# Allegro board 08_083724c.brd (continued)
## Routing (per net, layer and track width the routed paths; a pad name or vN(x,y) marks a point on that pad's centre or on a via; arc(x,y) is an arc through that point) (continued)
PB_07/TM0_TMR0/SPI2_SEL4B/FPLL2: length 59.8
  TOP w0.14: v1(17.86,59.11) 17.49,59.11 17.22,59.37 17.22,60.67 17.08,60.81 R41.2 ; U1.N6 v1(46.15,51.82)
  L10_SIG4 w0.114: v1(46.15,51.82) 46.56,52.22 47.14,52.22 47.35,52.43 47.35,54.36 47.6,54.61 47.95,54.61 48.13,54.8 48.13,55.19 47.9,55.42 47.57,55.42 47.37,55.63 47.37,56.01 47.02,56.36 47.02,56.77 46.51,57.28 46.51,57.56 46.28,57.78 46,57.78 45.72,58.06 45.72,58.37 45.52,58.57 44.81,58.57 43.87,59.51 43.15,59.51 42.02,60.64 34.87,60.64 34.76,60.64 34.58,60.64 33.78,59.84 33.78,58.88 33.53,58.62 32.18,58.62 32.03,58.47 30.43,58.47 30.43,58.47 29.21,58.47 28.5,57.76 28.5,56.54 28.5,56.54 28.5,55.95 28.5,55.94 27.84,55.28 27.84,54.71 26.23,53.11 23.83,53.11 17.86,59.08 v1(17.86,59.11)
  BOTTOM w0.14: v1(17.86,59.11) 18.16,59.11 18.62,59.57 18.62,61.77 16.5,63.9 P8.23
PB_08/TMR1/SPI1_SEL4B/FPLL3_REF: length 57.9
  TOP w0.14: U1.L3 v1(48.55,49.42)
  L10_SIG4 w0.114: v1(17.22,64.31) 20.9,60.63 20.9,60.02 23.22,57.71 23.47,57.71 25.35,59.59 25.35,59.86 25.35,59.86 25.35,60.76 27.46,62.87 38.56,62.87 38.98,63.28 43.01,63.28 43.76,62.53 46.56,62.53 48.11,60.99 49.02,60.99 50.62,59.39 50.62,58.73 51.82,57.53 51.82,52.3 50.52,51 50.14,51 v1(48.55,49.42)
  BOTTOM w0.14: v1(17.22,64.31) 16.87,64.66 16.87,68.2 P8.25
PB_09/TM0_TMR2/EMSIO_WP/ETH0_PT: length 25.7
  TOP w0.14: U1.M3 v1(48.55,51.02)
  L3_SIG1 w0.114: v1(40.5,66.55) 40.2,66.55 40.08,66.44 40.08,63.27 40.41,62.94 40.41,61.01 41.5,59.92 41.5,55.42 41.76,55.16 41.76,54 41.94,53.82 44.04,53.82 44.15,53.71 44.15,51.69 44.42,51.41 46.46,51.41 46.56,51.31 46.56,50.88 46.81,50.62 47.88,50.62 48.2,50.94 v1(48.55,51.02)
  BOTTOM w0.14: P8.119 v1(40.5,66.55)
PB_10/TM0_TMR3/SPI1_D2: length 48.1
  TOP w0.14: U1.K3 v1(48.55,48.62)
  L10_SIG4 w0.114: v1(48.55,48.62) 48.43,48.98 48.16,49.25 48.16,49.68 48.97,50.49 48.97,51.18 49.2,51.41 50.37,51.41 50.6,51.64 50.6,56.1 50.48,56.21 48.39,56.21 48.16,56.44 48.16,57.61 47.95,57.81 47.57,57.81 47.35,58.04 47.35,58.32 47.04,58.62 46.79,58.62 46.53,58.88 46.53,59.96 45.54,60.95 42.94,60.95 42.78,61.1 42.61,61.28 30.19,61.28 27.86,58.95 27.86,56.41 26.82,55.37 26.2,55.37 v2(24.79,53.96)
  BOTTOM w0.14: U6.C4 22.16,54.91 24.66,54.91 R47.2 v2(24.79,53.96)
PB_11/TM0_TMR4/SPI1_D3: length 51.7
  TOP w0.14: U1.L2 v1(49.35,49.42)
  L10_SIG4 w0.114: v1(49.35,49.42) 49.7,49.42 52.13,51.85 52.13,58.93 48.21,62.85 43.89,62.85 43.14,63.6 38.81,63.6 38.39,63.18 27.17,63.18 23.32,59.33 v2(23.32,58.34)
  BOTTOM w0.14: U6.D4 22.17,55.93 R48.2 24.79,56.75 24.59,56.95 23.95,56.95 23.32,57.58 v2(23.32,58.34)
PB_12/TM0_TMR5/SPI5_CLK/PWM0__1: length 57.6
  TOP w0.14: U1.M6 v1(46.15,51.02)
  L10_SIG4 w0.114: v1(46.15,51.02) 46.54,51.41 48.69,51.41 48.97,51.69 48.97,55.17 48.72,55.42 48.35,55.42 48.16,55.62 48.16,55.96 47.88,56.24 47.65,56.24 47.37,56.51 47.37,57.53 47.09,57.81 46.74,57.81 46.53,58.01 46.53,58.41 46.34,58.6 45.95,58.6 45.57,58.98 45.16,58.98 44.91,59.23 44.91,59.8 44.08,60.63 42.81,60.63 42.48,60.96 33.58,60.96 32.31,59.69 29.11,59.69 28.18,58.76 28.18,58.32 28.18,58.31 28.18,56.07 27.52,55.41 27.52,55.15 27.52,54.84 26.1,53.42 23.96,53.42 18.36,59.02 18.36,59.99 18.24,60.12 v1(17.86,60.12)
  BOTTOM w0.14: R178.2 14.94,60.12 v1(17.86,60.12)
PB_12/TM0_TMR5/SPI5_CLK/PWM0_DH: length 5
  BOTTOM w0.14: R178.1 12.52,64.81 12.52,65.61 12.97,66.07 13.23,66.07 13.5,66.33 P8.11
PB_13/TM0_TMR6/SPI5_CITO/PWM0_D: length 57
  TOP w0.14: U1.K2 v1(49.35,48.62)
  L10_SIG4 w0.114: v1(14,66.55) 13.73,66.55 13.61,66.43 13.61,65.41 14.33,64.69 17.4,64.69 17.65,64.44 20.19,64.44 20.7,63.93 43.26,63.93 44.02,63.17 48.4,63.17 52.45,59.12 52.45,51.72 v1(49.35,48.62)
  BOTTOM w0.14: P8.13 v1(14,66.55)
PB_14/TM0_TMR7/SPI5_COTI/PWM0_S: length 59.7
  TOP w0.14: U1.L4 v1(47.75,49.42)
  L10_SIG4 w0.114: v1(47.75,49.42) 47.85,49.05 48.16,48.74 48.16,48.49 48.41,48.23 49.53,48.23 52.79,51.49 52.79,59.26 48.55,63.5 44.19,63.5 43.5,64.19 20.88,64.19 20.37,64.69 17.79,64.69 17.52,64.96 17.51,64.96 16.99,65.48 14.61,65.48 v1(14,66.09)
  BOTTOM w0.14: P8.15 14.5,66.33 14.25,66.09 v1(14,66.09)
PB_15/TM0_TMR8/SPI5_SEL1B/PWM0_: length 62.5
  TOP w0.14: U1.L5 v1(46.95,49.42)
  L10_SIG4 w0.114: v1(46.95,49.42) 47.37,49 47.37,48.46 47.62,48.21 47.93,48.21 48.16,47.98 48.16,47.65 48.39,47.42 49.5,47.42 49.73,47.65 49.73,47.93 53.11,51.3 53.11,59.39 48.67,63.83 44.31,63.83 43.71,64.43 21.86,64.43 21.51,64.77 21.51,66.5 21.07,66.94 16.86,66.94 16.01,66.09 15.45,66.09 v1(15,66.55)
  BOTTOM w0.14: P8.17 v1(15,66.55)
PC_00/SPI2_CITO_D1: length 35.4
  TOP w0.14: P8.94 34.25,66.84 34.13,66.73 34.13,65.48 34.01,65.35 33.8,65.35 v1(33.5,65.05) ; U1.U5 v1(46.95,55.02)
  L5_SIG2 w0.114: v1(46.95,55.02) 47.36,55.42 47.93,55.42 48.16,55.65 48.16,55.96 48.41,56.21 48.67,56.21 48.95,56.49 48.95,56.77 49.2,57.02 49.48,57.02 49.73,57.28 49.73,58.01 50.52,58.8 50.52,59.97 48.79,61.7 47.21,61.7 44.29,64.62 42.19,64.62 41.25,65.56 41.25,66.85 40.69,67.41 33.7,67.41 32.67,66.38 32.67,65.46 33.09,65.05 v1(33.5,65.05)
PC_01/SPI2_COTI_D0: length 29.1
  TOP w0.14: P8.96 34.75,66.79 34.85,66.69 34.85,65.72 34.71,65.58 v1(34.5,65.58) ; U1.V4 v1(47.75,55.82)
  L5_SIG2 w0.114: v1(47.75,55.82) 47.75,56.13 48.16,56.54 48.16,56.85 48.97,57.66 48.97,58.32 49.25,58.6 49.62,58.6 49.73,58.71 49.73,60.23 48.6,61.37 47.09,61.37 44.17,64.29 41.91,64.29 40.92,65.28 40.92,66.78 40.59,67.11 35.19,67.11 34.87,66.79 34.87,65.96 v1(34.5,65.58)
PC_02/SPI2_D2: length 33.8
  TOP w0.14: P8.98 35.25,66.84 35.13,66.73 35.13,65.46 34.75,65.07 v1(34.5,65.07) ; U1.W1 v1(50.15,56.62)
  L8_SIG3 w0.114: v1(34.5,65.07) 34.87,65.45 34.87,67.04 35.57,67.74 38.62,67.74 39.19,67.17 39.19,63.86 40.08,62.97 45.43,62.97 46.63,61.77 49.86,61.77 52.12,59.51 52.12,57.28 51.46,56.62 v1(50.15,56.62)
PC_03/SPI2_D3: length 28.1
  TOP w0.14: v1(35.5,65.58) 35.85,65.93 35.85,66.69 35.75,66.79 P8.100 ; U1.R6 v1(46.15,53.42)
  L3_SIG1 w0.114: v1(46.15,53.42) 45.81,53.53 45.54,53.8 45.19,53.8 44.98,54 44.98,54.36 44.72,54.62 42.69,54.62 42.57,54.74 42.57,55.22 42.37,55.42 41.97,55.42 41.78,55.6 41.78,58.75 41.94,58.9 41.94,59.99 41.38,60.55 41.38,66.7 40.77,67.31 36.49,67.31 36.02,66.84 36.02,65.7 35.9,65.58 v1(35.5,65.58)
PC_04/SPI2_CLK/TM0_ACLK1: length 4.7
  TOP w0.14: R175.1 32.97,65.05 33.17,65.26 33.2,65.26 33.8,65.86 33.8,65.88 33.85,65.93 33.85,66.69 33.75,66.79 P8.92
PC_04/SPI2_CLK/TM0_ACLK1_X: length 25.6
  TOP w0.14: v1(32.08,63.55) 32.08,63.19 32.22,63.05 R175.2 ; U1.V2 v1(49.35,55.82)
  BOTTOM w0.14: v1(32.08,63.55) 32.97,62.66 36.96,62.66 38.58,61.04 38.58,56.36 38.72,56.22 43.86,56.22 44.15,55.93 44.15,55.55 44.27,55.42 48.96,55.42 v1(49.35,55.82)
PC_05/SPI2_SEL1B/SPI2_TS*: length 31.3
  TOP w0.14: v1(35.5,65.07) 36.13,65.71 36.13,66.73 36.25,66.84 P8.102 ; v1(50.5,57.4) 50.47,57.38 50.11,57.38 U1.Y1
  L8_SIG3 w0.114: v1(35.5,65.07) 35.13,65.44 35.13,66.79 35.7,67.36 38.43,67.36 38.87,66.92 38.87,63.08 39.83,62.13 45.82,62.13 46.49,61.46 49.7,61.46 51.79,59.36 51.79,58.7 v1(50.5,57.4)
PC_06/SPI2_SEL2B/ETH0_PTPPPS2/E: length 31
  TOP w0.14: U1.V1 v1(50.15,55.82) ; v1(36.5,65.58) 36.8,65.88 36.8,65.9 36.85,65.95 36.85,66.69 36.75,66.79 P8.104
  L8_SIG3 w0.114: v1(50.15,55.82) 49.76,56.21 49.76,57.23 50.67,58.14 50.67,59.54 49.07,61.14 46.3,61.14 45.64,61.8 39.67,61.8 36.97,64.5 36.97,65.39 36.78,65.58 v1(36.5,65.58)
  BOTTOM w0.14: v1(36.5,65.58) 37.36,64.73 37.91,64.73 38.11,64.93 38.11,65.07 39.5,66.46 P8.115
PC_07/SPI2_SEL3B/ETH0_PTPPPS3/E: length 32.5
  TOP w0.14: U1.T2 v1(49.35,54.22) ; P8.106 37.25,66.84 37.13,66.73 37.13,65.71 v1(36.5,65.07)
  L8_SIG3 w0.114: v1(49.35,54.22) 48.95,54.62 48.95,57.56 49.23,57.84 49.58,57.84 49.73,57.99 49.73,59.39 48.3,60.82 46.11,60.82 45.49,61.44 39.55,61.44 36.5,64.49 v1(36.5,65.07)
  BOTTOM w0.14: P8.117 40,66.51 38.56,65.07 38.56,64.82 38.18,64.44 37.13,64.44 v1(36.5,65.07)
PC_08/SPI2_RDY: length 26.9
  TOP w0.14: U1.V3 v1(48.55,55.82) ; P8.108 37.64,68.22 37.64,66.43 v1(37.97,66.09)
  L8_SIG3 w0.114: v1(37.97,66.09) 37.08,66.98 36.33,66.98 36.02,66.66 36.02,64.49 39.41,61.1 45.33,61.1 45.94,60.48 48.13,60.48 48.95,59.66 48.95,58.06 48.13,57.25 48.13,56.44 48.55,56.02 v1(48.55,55.82)
PC_09/SPI0_CLK: length 4.6
  TOP w0.14: P8.112 38.75,66.79 38.85,66.69 38.85,65.87 38.43,65.46 38.43,64.3 R61.1
PC_09/SPI0_CLK_X: length 14.9
  TOP w0.14: v1(40.97,62.6) 40.52,63.05 R61.2 ; U1.V6 v1(46.15,55.82)
  BOTTOM w0.14: v1(40.97,62.6) 41.72,63.35 43.28,63.35 45.75,60.88 45.75,56.22 v1(46.15,55.82)
PC_10/SPI0_CITO: length 17.5
  TOP w0.14: P8.114 39.25,66.84 39.13,66.73 39.13,65.68 38.84,65.38 38.84,64.39 39.52,63.7 40.69,63.7 41.61,62.79 41.61,62.51 42.2,61.92 43.43,61.92 v1(44.78,60.57) ; U1.Y4 v1(47.75,57.42)
  L5_SIG2 w0.114: v1(47.75,57.42) 47.74,57.42 47.32,57.84 47.32,59.23 47,59.55 45.99,59.55 45.42,60.12 45.03,60.12 44.91,60.25 v1(44.78,60.57)
PC_11/SPI0_COTI: length 16.6
  TOP w0.14: U1.V7 v1(45.35,55.82) ; v1(42.19,62.6) 42.19,63.07 40.92,64.34 39.57,64.34 39.24,64.67 39.24,65.3 39.75,65.81 P8.116
  BOTTOM w0.14: v1(42.19,62.6) 44.93,59.86 44.93,56.23 v1(45.35,55.82)
PC_12/SPI0_SEL1B/SPI0_TS*: length 16.2
  TOP w0.14: P8.118 40.25,66.84 40.08,66.67 40.08,65.48 v1(39.68,65.07) ; U1.AB3 v1(48.55,59.02)
  L5_SIG2 w0.114: v1(39.68,65.07) 39.76,64.69 41.12,63.33 43.7,63.33 46.63,60.4 48.21,60.4 48.55,60.06 v1(48.55,59.02)
PC_13/SPI0_RDY: length 16.4
  TOP w0.14: v1(40.5,65.07) 40.97,65.07 41.13,65.24 41.13,66.73 41.25,66.84 P8.122 ; U1.AB2 v1(49.35,59.02)
  L5_SIG2 w0.114: v1(40.5,65.07) 41.59,63.98 43.98,63.98 46.92,61.05 48.46,61.05 49.35,60.16 v1(49.35,59.02)
PC_14/SPI0_SEL2B/EMSI0_VDD1_SEL: length 17.4
  TOP w0.14: U1.AA3 v1(48.55,58.22) ; v1(40.5,65.58) 40.71,65.58 40.85,65.72 40.85,66.69 40.75,66.79 P8.120
  L5_SIG2 w0.114: v1(48.55,58.22) 48.55,58.46 48.95,58.85 48.95,60.12 48.33,60.73 46.79,60.73 43.87,63.65 41.31,63.65 40.08,64.88 40.08,65.27 40.18,65.36 v1(40.5,65.58)
PC_15/SPI1_CLK/TRACE0_CLK/TM0_1: length 55.6
  TOP w0.14: U1.W3 v1(48.55,56.62)
  L10_SIG4 w0.114: v1(48.55,56.62) 48.72,57.05 48.72,57.51 48.16,58.06 48.16,59.11 47.84,59.42 47.7,59.42 47.45,59.68 47.45,60.12 45.99,61.58 43.25,61.58 42.92,61.91 27.98,61.91 26.31,60.25 26.31,58.01 24.87,56.57 22.99,56.57 19.76,59.79 19.76,60.27 18.75,61.29 17.45,61.29 16.33,60.17 16.33,59.41 13.99,57.07 13.99,52.83 12.9,51.74 v2(12.9,50.35)
  BOTTOM w0.14: R62.2 v2(12.9,50.35)
PC_15/SPI1_CLK/TRACE0_CLK/TM0_A: length 21
  L3_SIG1 w0.114: v1(11,66.55) 10.62,66.55 9.98,65.91 9.98,62.07 13.03,59.02 13.03,51.92 v2(13.6,51.35)
  BOTTOM w0.14: v2(13.6,51.35) R62.1 14.44,51.36 R43.1 ; P8.1 v1(11,66.55)
PD_00/SPI1_CITO/TRACE0_D00: length 58.1
  TOP w0.14: U1.AA4 v1(47.75,58.22)
  L3_SIG1 w0.114: v1(11,66.09) 10.67,66.09 10.3,65.72 10.3,62.24 13.41,59.13 13.41,57.84 14.17,57.07 v2(14.74,57.07)
  L10_SIG4 w0.114: v1(47.75,58.22) 47.65,58.55 47.32,58.88 47.32,59.17 47,59.49 47,60.06 45.8,61.26 43.12,61.26 42.79,61.59 30.05,61.59 27.48,59.03 27.48,57.66 26.01,56.18 22.92,56.18 19.38,59.72 19.38,60.21 18.65,60.94 17.63,60.94 16.69,60 16.69,59.02 v2(14.74,57.07)
  BOTTOM w0.14: P8.3 11.5,66.33 11.25,66.09 v1(11,66.09) ; R49.2 v2(14.74,57.07)
PD_01/SPI1_COTI/TRACE0_D01: length 64.6
  TOP w0.14: U1.Y2 v1(49.35,57.42)
  L10_SIG4 w0.114: v1(12,66.55) 12.45,66.1 12.45,64.92 12.78,64.59 13.33,64.59 14.12,63.8 14.12,59.28 v2(14.81,58.6) 15.95,59.74 15.95,60.35 17.27,61.67 18.84,61.67 20.14,60.37 20.14,59.86 23.05,56.95 24.79,56.95 25.98,58.14 25.98,60.45 27.76,62.23 43.05,62.23 43.38,61.9 46.18,61.9 47.73,60.35 48.34,60.35 48.97,59.72 48.97,57.8 v1(49.35,57.42)
  BOTTOM w0.14: P8.5 v1(12,66.55) ; U6.D3 20.14,55.91 20.14,56.82 18.87,58.09 15.32,58.09 v2(14.81,58.6)
PD_02/SPI1_SEL1B/TRACE0_D02/SPI: length 62.3
  TOP w0.14: U1.T6 v1(46.15,54.22)
  L3_SIG1 w0.114: v2(16.51,54.72) 15.9,55.34 15.9,58.16 11.38,62.69 11.38,65.91 11.53,66.07 v1(12,66.07)
  L10_SIG4 w0.114: v1(46.15,54.22) 46.54,54.35 46.82,54.64 47.14,54.64 47.35,54.84 47.35,55.17 47.12,55.4 46.75,55.4 46.56,55.59 46.56,56.74 46.3,57 46,57 45.75,57.25 45.75,57.58 45.52,57.81 44.37,57.81 44.15,58.04 44.15,58.37 43.92,58.6 43.56,58.6 41.83,60.33 35.97,60.33 34.34,58.7 34.09,58.7 33.76,58.37 33.76,58.12 33.45,57.81 32.33,57.81 31.99,58.15 31.11,58.15 30.81,57.85 30.81,57.12 29.17,55.49 28.49,55.49 28.16,55.15 28.16,54.52 26.42,52.79 23.7,52.79 21.76,54.72 v2(16.51,54.72)
  BOTTOM w0.14: v1(12,66.07) 12.23,66.07 12.5,66.33 P8.7 ; v2(16.51,54.72) R44.2 19.14,53.9 U6.C2
PD_03/SPI1_RDY/TRACE0_D03: length 52.1
  TOP w0.14: U1.W2 v1(49.35,56.62)
  L10_SIG4 w0.114: v1(13,66.55) 13.37,66.17 13.37,65.21 14.76,63.83 17.13,63.83 20.52,60.43 20.52,59.93 23.12,57.33 24.71,57.33 25.67,58.28 25.67,59.3 25.67,60.63 27.59,62.55 38.77,62.55 39.19,62.97 42.82,62.97 43.57,62.22 46.37,62.22 47.92,60.67 48.78,60.67 49.73,59.72 49.73,57 v1(49.35,56.62)
  BOTTOM w0.14: P8.9 v1(13,66.55)
PD_04/SPI1_SEL2B/SMSI0_SD_VDD1_: length 50.5
  TOP w0.14: v1(53.67,58.03) 49.96,58.03 U1.AA1
  L10_SIG4 w0.114: v1(53.67,58.03) 54.33,58.69 54.33,59.17 52.08,61.42 52.08,61.84 51.7,62.22 50.73,62.22 48.78,64.16 44.42,64.16 43.89,64.69 22.89,64.69 22.48,65.1 22.48,66.88 22.07,67.28 16.73,67.28 v1(16,66.55)
  BOTTOM w0.14: P8.21 v1(16,66.55)
PD_05/SPI1_SEL3B/EMSIO_UHS1_SWV: length 85.4
  TOP w0.14: U9.E3 17.04,2.14 R155.2 R156.1 v2(16.07,1.26) ; U1.W5 v1(46.17,56.59)
  L10_SIG4 w0.114: v1(46.17,56.59) 45.77,56.72 45.47,57.02 44.37,57.02 44.15,57.25 44.15,57.58 43.92,57.81 43.56,57.81 43.33,58.04 43.33,58.37 41.69,60.01 36.13,60.01 34.54,58.42 34.54,58.06 34.29,57.81 33.99,57.81 33.76,57.58 33.76,57.28 33.48,57 32.69,57 32.44,57.24 31.97,57.24 31.72,57 31.17,57 29.34,55.17 28.63,55.17 28.47,55.02 28.47,53.62 23.65,48.8 23.65,38.54 19.51,34.39 19.51,4.75 18.75,3.99 18.75,2.72 18.11,2.08 16.9,2.08 v2(16.07,1.26)
PD_06/CAN0_RX/TM0_AC12: length 17.1
  TOP w0.14: P8.178 v1(55.25,66.55) ; U1.U2 v1(49.35,55.02)
  L3_SIG1 w0.114: v1(55.25,66.55) 54.41,65.71 53.04,65.71 51.9,64.57 51.9,63.33 50.69,62.12 50.69,60.23 49.75,59.3 49.75,55.67 49.44,55.36 v1(49.35,55.02)
PD_07/CAN0_TX: length 18
  TOP w0.14: P8.176 v1(54.75,66.55) ; U1.U4 v1(47.75,55.02)
  L3_SIG1 w0.114: v1(54.75,66.55) 54.24,66.04 52.78,66.04 51.1,64.36 51.1,63.17 50.37,62.43 50.37,60.71 48.95,59.3 48.95,55.61 48.74,55.4 48.23,55.4 48.07,55.23 v1(47.75,55.02)
PD_08/CAN1_RX/TM0_AC14: length 17.4
  TOP w0.14: P8.184 v1(56.75,66.55) ; U1.U1 v1(50.15,55.02)
  L3_SIG1 w0.114: v1(50.15,55.02) 50.35,55.12 50.48,55.18 51.03,55.73 51.03,56.13 52.12,57.23 52.12,61.82 54.05,63.75 54.05,64.41 55.32,65.68 56.49,65.68 56.75,65.94 v1(56.75,66.55)
PD_09/CAN1_TX: length 20.7
  TOP w0.14: P8.182 v1(56.25,66.28) ; U1.T4 v1(47.75,54.22)
  L3_SIG1 w0.114: v1(47.75,54.22) 48.09,54.29 48.42,54.62 49.48,54.62 49.73,54.86 49.73,55.22 49.93,55.42 50.28,55.42 50.61,55.74 50.61,56.71 50.11,57.2 50.11,58.28 51,59.51 51,61.85 52.25,63.09 52.25,64.36 53.26,65.38 54.56,65.38 55.19,66.01 55.98,66.01 v1(56.25,66.28)
PD_10/XSPI0_CITO/XSPIO_D1: length 23.1
  TOP w0.14: U1.E22 v1(32.55,44.62)
  L8_SIG3 w0.114: v1(32.55,44.62) 31.85,45.31 30.1,45.31 27.48,42.7 24.61,42.7 23.96,43.35 v2(13.6,43.35)
  BOTTOM w0.14: R32.2 14.43,43.36 R145.2 v2(13.6,43.35)
PD_11/XSPI0_COTI_D0/XSPI0_D0: length 22
  TOP w0.14: U1.E21 v1(33.35,44.62)
  L3_SIG1 w0.114: v2(19.42,49.46) 19.42,47.05 24.13,42.34 28.19,42.34 29.21,43.36 30.73,43.36 32.39,45.02 32.95,45.02 v1(33.35,44.62)
  BOTTOM w0.14: R28.2 v2(19.42,49.46)
PD_12/XSPI0_D2: length 14.9
  TOP w0.14: U1.H19 v1(34.95,47.02)
  L8_SIG3 w0.114: v1(34.95,47.02) 34.57,46.63 33.99,46.63 33.76,46.41 33.76,45.24 33.55,45.03 33.15,45.03 32.97,44.86 32.97,44.42 32.77,44.22 32.13,44.22 31.95,44.4 29.82,44.4 25.76,40.34 v2(25.76,39.87)
  BOTTOM w0.14: R33.2 v2(25.76,39.87)
PD_13/XSPI0_D3: length 11.4
  TOP w0.14: U1.G20 v1(34.15,46.22)
  L5_SIG2 w0.114: v1(34.15,46.22) 34.07,45.86 33.75,45.54 33.75,45.28 33.48,45.02 31.95,45.02 31.57,45.39 30.09,45.39 v2(26.54,41.83)
  BOTTOM w0.14: R29.2 v2(26.54,41.83)
PD_14/XSPI0_CLK/TM0_ACLK4: length 28
  L8_SIG3 w0.114: v2(13.6,36.87) 12.9,37.57 12.9,38.66 14.17,39.93 14.17,40.56 13.92,40.82 13.28,40.82 12.65,41.45 12.65,43.74 13.54,44.63 24.33,44.63 v4(24.97,45.26)
  BOTTOM w0.14: R23.1 14.44,36.88 R19.1 v2(13.6,36.87) ; v4(24.97,45.26) 25.6,45.9 28.28,45.9 R63.1
PD_14/XSPI0_CLK/TM0_ACLK4_X: length 4.4
  TOP w0.14: U1.F21 v1(33.35,45.42)
  BOTTOM w0.14: v1(33.35,45.42) 32.95,45.82 30.47,45.82 R63.2
PD_15/XSPI0_CLKB: length 31.6
  TOP w0.14: U1.F22 v1(32.55,45.42)
  L8_SIG3 w0.114: v1(32.55,45.42) 32.23,45.42 31.9,45.75 28.78,45.75 26.52,43.48 24.84,43.48 24.14,44.18 13.67,44.18 13.03,43.55 13.03,42.06 13.26,41.83 13.92,41.83 14.72,41.04 14.72,39.71 v2(13.54,38.53)
  BOTTOM w0.14: v2(13.54,38.53) 14.05,38.02 R21.1 R25.1
PE_00/XSPI0_D4/TM0_ACLK4: length 10.7
  TOP w0.14: U1.G21 v1(33.35,46.22)
  L8_SIG3 w0.114: v2(25.76,43.97) 25.76,44.47 27.52,46.23 31.95,46.23 32.36,45.82 32.96,45.82 v1(33.35,46.22)
  BOTTOM w0.14: v2(25.76,43.97) R30.2
PE_01/XSPI0_D5: length 20
  TOP w0.14: U1.J19 v1(34.95,47.82)
  L5_SIG2 w0.114: v2(20.56,48.32) 20.56,46.72 22.63,44.65 25.15,44.65 27.03,46.53 28.12,46.53 29,47.42 33.52,47.42 33.75,47.65 33.75,47.98 33.99,48.21 34.56,48.21 v1(34.95,47.82)
  BOTTOM w0.14: R34.2 v2(20.56,48.32)
PE_02/XSPI0_D6: length 22.2
  TOP w0.14: U1.J18 v1(35.75,47.82)
  L5_SIG2 w0.114: v1(35.75,47.82) 35.35,47.42 33.98,47.42 33.76,47.19 33.76,46.89 33.48,46.62 28.73,46.62 28.19,46.08 27.15,46.08 25.3,44.22 22.37,44.22 v2(18.28,48.32)
  BOTTOM w0.14: R31.2 v2(18.28,48.32)
PE_03/XSPI0_D7: length 19.2
  TOP w0.14: U1.G22 v1(32.55,46.22)
  L8_SIG3 w0.114: v1(32.55,46.22) 32.13,46.63 26.16,46.63 25.43,45.9 24.52,45.9 23.95,45.33 v2(15.49,45.33)
  BOTTOM w0.14: R35.2 v2(15.49,45.33)
PE_04/XSPI0_DQSB_RWDS*: length 29.1
  TOP w0.14: U1.H20 v1(34.15,47.02) ; TP7.1 v2(16.99,35.11)
  L5_SIG2 w0.114: v1(34.15,47.02) 34.06,46.69 33.76,46.38 33.76,46.08 33.5,45.82 28.95,45.82 25.03,41.9 20.21,41.9 18.24,39.93 18.24,36.36 v2(16.99,35.11)
  BOTTOM w0.14: v2(16.99,35.11) TP7.1 R40.1 R27.2
PE_05/XSPI0_SEL1*: length 31.6
  TOP w0.14: U1.K19 v1(34.95,48.62)
  L8_SIG3 w0.114: v1(34.95,48.62) 34.54,48.21 32.23,48.21 31.75,47.73 27.37,47.73 26.78,47.14 24.41,47.14 23.23,45.96 14.3,45.96 12.3,43.96 12.3,41.01 13,40.32 v2(13.6,40.32)
  BOTTOM w0.14: v2(13.6,40.32) R18.2 14.44,40.31 R22.1
PE_06/XSPI0_SEL2B/SMSI0_LED_CNT: length 25.3
  TOP w0.14: TP5.1 v2(23.29,35.11) ; U1.K17 v1(36.55,48.62)
  L5_SIG2 w0.114: v1(36.55,48.62) 36.95,48.22 36.95,46.78 36.83,46.66 36.42,46.66 36.15,46.39 36.15,44.4 35.97,44.22 34.82,44.22 34.55,43.95 34.55,43.61 34.36,43.42 32.77,43.42 24.47,35.11 v2(23.29,35.11)
  BOTTOM w0.14: R24.1 TP5.1 v2(23.29,35.11)
PE_07/XSPI1_CITO_D1: length 42
  TOP w0.14: P8.6 12.25,66.79 12.35,66.69 12.35,65.72 12.21,65.58 v1(12,65.58) ; U1.H21 v1(33.35,47.02)
  L3_SIG1 w0.114: v1(33.35,47.02) 32.95,47.42 31.44,47.42 28.39,44.36 26.94,44.36 26.01,43.43 24.61,43.43 22.17,45.87 22.17,48.26 18.62,51.82 18.62,55.11 16.24,57.48 16.24,58.28 11.89,62.64 11.89,64.57 11.63,64.82 11.63,65.47 11.75,65.58 v1(12,65.58)
PE_08/XSPI1_COTI_DO: length 41.8
  TOP w0.14: v1(11,65.07) 11.63,65.71 11.63,66.73 11.75,66.84 P8.4 ; U1.H22 v1(32.55,47.02)
  L3_SIG1 w0.114: v1(11,65.07) 11,62.53 14.17,59.36 14.17,58.34 14.43,58.09 15.06,58.09 15.56,57.59 15.56,54.43 21.06,48.93 21.06,46.46 24.44,43.08 26.19,43.08 26.85,43.74 28.4,43.74 31.67,47.02 v1(32.55,47.02)
PE_09/XSPI1_D2: length 42.8
  TOP w0.14: P8.8 12.75,66.84 12.63,66.73 12.63,65.31 12.4,65.07 v1(12,65.07) ; U1.K18 v1(35.75,48.62)
  L3_SIG1 w0.114: v1(12,65.07) 13.16,63.91 13.16,62.33 16.93,58.56 16.93,57.77 19.3,55.39 19.3,52.14 23.55,47.9 23.55,45.72 24.59,44.68 25.22,44.68 26.59,46.05 28.8,46.05 30.96,48.21 35.08,48.21 35.48,48.62 v1(35.75,48.62)
PE_10/XSPI1_D3: length 36.1
  TOP w0.14: P8.10 13.25,66.79 13.35,66.69 13.35,65.72 13.21,65.58 v1(13,65.58) ; U1.L19 v1(34.95,49.42)
  L3_SIG1 w0.114: v1(13,65.58) 12.61,65.58 12.5,65.47 12.5,65.02 12.84,64.68 13.3,64.68 14.02,63.96 15.68,63.96 16.33,63.3 16.33,62.7 18.76,60.27 18.76,57.94 22.64,54.05 22.64,52.52 24.75,50.42 31.49,50.42 31.97,49.94 34.43,49.94 v1(34.95,49.42)
PE_11/XSPI1_CLK*: length 28.6
  TOP w0.14: v1(15.82,63.3) 15.82,63.8 16.63,64.61 16.63,66.73 16.75,66.84 P8.24
  L3_SIG1 w0.114: v1(15.82,63.3) 15.82,62.66 18.36,60.12 18.36,57.79 20.33,55.82 20.33,52.57 24.64,48.26 v4(24.97,47.8)
  BOTTOM w0.14: R144.2 v4(24.97,47.8)
PE_12/XSPI1_CLK/FPLL2_REF_CLK: length 29.6
  TOP w0.14: P8.26 17.25,66.5 v1(17.22,66.47)
  L5_SIG2 w0.114: v4(24.97,46.53) 23.95,47.55 23.95,48.44 16.41,55.98 16.41,65.66 v1(17.22,66.47)
  BOTTOM w0.14: R177.2 v4(24.97,46.53)
PE_13/XSPI1_D4: length 36.2
  TOP w0.14: P8.12 13.75,66.84 13.63,66.73 13.63,65.42 13.28,65.07 v1(13,65.07) ; U1.L18 v1(35.75,49.42)
  L3_SIG1 w0.114: v1(13,65.07) 13.54,65.07 14.34,64.27 15.81,64.27 16.75,63.33 16.75,62.73 19.08,60.4 19.08,58.07 22.96,54.19 22.96,52.65 24.87,50.75 31.61,50.75 32.09,50.27 34.89,50.27 v1(35.75,49.42)
PE_14/XSPI1_D5: length 34.5
  TOP w0.14: U1.M18 v1(35.75,51.02) ; P8.14 14.25,66.79 14.35,66.69 14.35,65.93 v1(14,65.58)
  L3_SIG1 w0.114: v1(14,65.58) 14,65.2 14.58,64.62 15.91,64.62 17.11,63.43 17.11,62.83 19.4,60.53 19.4,58.24 23.29,54.34 23.29,52.77 24.99,51.08 31.88,51.08 32.36,50.6 35.34,50.6 v1(35.75,51.02)
PE_15/XSPI1_D6: length 40
  TOP w0.14: P8.16 14.75,66.84 14.63,66.73 14.63,65.69 v1(12.75,63.8) ; U1.J22 v1(32.55,47.82)
  L3_SIG1 w0.114: v1(32.55,47.82) 31.2,47.82 28.96,45.57 26.64,45.57 25.32,44.25 24.36,44.25 23.16,45.44 23.16,47.79 18.96,52 18.96,55.25 16.59,57.62 16.59,58.44 12.75,62.28 v1(12.75,63.8)
PF_00/XSPI1_D7: length 39.2
  TOP w0.14: v1(13.54,63.68) 13.54,64.16 14.8,65.42 15.16,65.42 15.35,65.61 15.35,66.69 15.25,66.79 P8.18 ; U1.K20 v1(34.15,48.62)
  L3_SIG1 w0.114: v1(34.15,48.62) 30.79,48.62 28.7,46.53 25.98,46.53 25.37,45.92 24.64,45.92 23.93,46.63 23.93,48 19.65,52.28 19.65,55.54 17.27,57.91 17.27,58.7 13.54,62.43 v1(13.54,63.68)
PF_01/XSPI1_DQS_RWDS*: length 50.2
  TOP w0.14: v1(11,65.58) 11.35,65.93 11.35,66.69 11.25,66.79 P8.2 ; U1.M17 v1(36.55,51.02)
  L3_SIG1 w0.114: v1(11,65.58) 10.73,65.58 10.62,65.47 10.62,62.41 13.79,59.23 13.79,58.09 14.3,57.58 14.93,57.58 15.24,57.27 15.24,54.3 19.94,49.6 19.94,47.04 24.26,42.72 28.02,42.72 31.91,46.62 34.3,46.62 34.54,46.86 34.54,47.29 34.67,47.42 35.18,47.42 35.36,47.6 35.36,47.95 35.61,48.21 36.06,48.21 36.15,48.31 36.15,50.62 v1(36.55,51.02)
PF_02/XSPI1_SEL1B: length 32.8
  TOP w0.14: P8.20 15.75,66.84 15.63,66.73 15.63,65.21 15.49,65.07 v1(15,65.07) ; U1.M19 v1(34.95,51.02)
  L3_SIG1 w0.114: v1(15,65.07) 15.91,65.07 17.48,63.51 17.48,62.99 19.71,60.75 19.71,58.4 23.64,54.48 23.64,52.88 25.1,51.42 34.55,51.42 v1(34.95,51.02)
PF_03/XSPI1_SEL2B/EMSI0_CD/TM0_: length 126.2
  TOP w0.14: v1(15.34,63.14) 15.34,64.08 16.35,65.09 16.35,66.69 16.25,66.79 P8.22 ; R60.1 v2(13.97,5.13) ; U1.L20 v1(34.15,49.42)
  L3_SIG1 w0.114: v1(34.15,49.42) 33.76,49.02 32.38,49.02 31.95,49.45 31.06,49.45 29.31,47.7 26.16,47.7 25.63,47.17 24.59,47.17 24.31,47.45 24.31,48.08 19.99,52.4 19.99,55.68 17.61,58.05 17.61,58.81 15.34,61.09 v1(15.34,63.14)
  L5_SIG2 w0.114: v2(13.97,5.13) 13.42,5.69 9.3,5.69 6.43,8.56 2.24,8.56 1.47,9.32 1.47,44.37 5.79,48.69 13.67,48.69 15.24,50.27 20.73,50.27 23.22,47.78 23.22,46.66 23.98,45.9 25.78,45.9 27.61,47.73 28.32,47.73 28.83,48.23 33.22,48.23 34.15,49.16 v1(34.15,49.42)
PF_04/LP0_CLK/FPLL_REF_CLK: length 4.1
  BOTTOM w0.14: R152.2 74,64.43 P8.253
PF_04/LP0_CLK/FPLL_REF_CLK_X: length 35.9
  TOP w0.14: U1.G2 49.36,46.2 v1(50.88,46.2)
  L5_SIG2 w0.114: v1(50.88,46.2) 50.88,46.55 50.99,46.66 53.04,46.66 55.78,49.4 56.87,49.4 57.71,50.24 58.04,50.24 59.06,51.26 59.06,54.82 59.94,55.7 63.43,55.7 66.77,59.04 69.61,59.04 71.83,61.26 v2(74.12,61.26)
  BOTTOM w0.14: R152.1 v2(74.12,61.26)
PF_05/LP0_ACK/TM0_ACI13: length 38.2
  TOP w0.14: U1.H1 v1(50.15,47.02)
  L5_SIG2 w0.114: v1(50.15,47.02) 52.83,47.02 55.7,49.89 56.06,49.89 58.74,52.57 58.74,55.42 60.16,56.83 64.11,56.83 66.63,59.36 69.47,59.36 74.12,64.01 74.37,64.01 74.9,64.54 74.9,66.07 v1(74.5,66.47)
  BOTTOM w0.14: P8.255 74.5,66.47 v1(74.5,66.47)
PF_06/LP0_D0: length 38.5
  TOP w0.14: U1.H3 v1(48.55,47.02)
  L5_SIG2 w0.114: v1(74.5,65.71) 73.11,64.33 70.7,64.33 63.84,57.47 59.9,57.47 58.11,55.68 58.11,53.54 57.43,52.86 56.62,52.86 51.99,48.23 50.04,48.23 49.73,47.93 49.73,47.65 49.5,47.42 48.96,47.42 v1(48.55,47.02)
  BOTTOM w0.14: P8.257 75,66.21 v1(74.5,65.71)
PF_07/LP0_D1: length 38.6
  TOP w0.14: U1.H2 v1(49.35,47.02)
  L5_SIG2 w0.114: v1(74.5,64.95) 74.5,64.87 69.37,59.74 66.57,59.74 63.98,57.15 60.03,57.15 58.43,55.55 58.43,52.7 56.09,50.37 55.63,50.37 52.69,47.44 50,47.44 49.58,47.02 v1(49.35,47.02)
  BOTTOM w0.14: P8.259 75.5,66.33 75.32,66.15 75.32,65.77 v1(74.5,64.95)
PF_08/LP0_D2: length 44.6
  TOP w0.14: U1.J4 v1(47.75,47.82)
  L5_SIG2 w0.114: v1(75.77,64.95) 76.12,65.3 76.12,66.42 75.24,67.31 74.19,67.31 73.85,66.97 73.85,66.21 72.68,65.04 70.51,65.04 64.25,58.78 61.65,58.78 60.97,58.1 59.63,58.1 57.47,55.94 57.47,53.88 57.09,53.49 56.21,53.49 51.74,49.02 48.35,49.02 48.15,48.81 48.15,48.48 47.75,48.08 v1(47.75,47.82)
  BOTTOM w0.14: v1(75.77,64.95) 75.77,65.33 76.09,65.66 76.09,66.46 76.02,66.54 76.02,68.3 P8.261
PF_09/LP0_D3: length 43.7
  TOP w0.14: U1.F1 50.18,45.39 v1(51.64,45.39)
  L5_SIG2 w0.114: v2(78.49,62.53) 76.64,60.68 75.45,60.68 74.82,60.06 73.01,60.06 70.22,57.26 66.5,57.26 61.23,51.99 61.23,50.27 60.79,49.83 59.72,49.83 57.91,48.03 56.97,48.03 54.33,45.39 v1(51.64,45.39)
  BOTTOM w0.14: P8.263 76.5,65.17 78.49,63.18 v2(78.49,62.53)
PF_10/LP1_CLK: length 3.8
  BOTTOM w0.14: v1(77.74,64.82) 77.99,65.07 77.99,66.28 77.62,66.65 77.62,68.2 P8.267
PF_10/LP1_CLK_X: length 39.3
  TOP w0.14: v2(77.67,62.53) 77.93,62.79 R151.1 ; U1.G3 v1(48.55,46.22)
  L5_SIG2 w0.114: v2(77.67,62.53) 76.23,61.09 75.31,61.09 74.6,60.38 72.82,60.38 70.79,58.34 67.07,58.34 62.22,53.49 60.14,53.49 59.77,53.12 59.77,50.95 58.42,49.61 57.97,49.61 54.19,45.82 50.72,45.82 50.33,46.22 v1(48.55,46.22)
PF_11/LP1_ACK: length 43.1
  TOP w0.14: v1(51.38,46.22) 51.38,46.43 51.2,46.62 U1.G1
  L5_SIG2 w0.114: v1(51.38,46.22) 54.13,46.22 57.84,49.92 58.25,49.92 59.38,51.05 59.38,54.1 59.92,54.64 62.85,54.64 66.92,58.7 70.66,58.7 72.69,60.73 74.42,60.73 75.18,61.49 75.87,61.49 v1(79.01,64.63)
  BOTTOM w0.14: v1(79.01,64.63) 78.37,65.27 78.37,66.41 78,66.78 P8.269
PF_12/LP1_D0: length 46.8
  TOP w0.14: U1.K5 v1(46.95,48.62)
  L5_SIG2 w0.114: v1(46.95,48.62) 47.35,49.01 47.35,49.58 47.57,49.81 49.56,49.81 49.89,49.48 51.73,49.48 55.63,53.37 55.63,54.54 59.5,58.42 60.81,58.42 61.52,59.13 64.16,59.13 70.38,65.35 70.71,65.35 70.94,65.58 70.94,67.03 71.56,67.65 76.78,67.65 v1(79.05,65.39)
  BOTTOM w0.14: v1(79.05,65.39) 79.07,65.39 79.07,65.39 78.69,65.77 78.69,66.6 78.5,66.79 P8.271
PF_13/LP1_D1: length 47.7
  TOP w0.14: U1.J5 v1(46.95,47.82)
  L5_SIG2 w0.114: v1(79.04,66.15) 77.2,68 70.46,68 69.09,66.62 69.09,64.58 64.12,59.61 60.24,59.61 55.26,54.62 55.26,53.45 51.66,49.85 49.94,49.83 49.68,50.09 47.09,50.09 46.56,49.56 46.56,48.46 46.95,48.07 v1(46.95,47.82)
  BOTTOM w0.14: v1(79.04,66.15) 79.07,66.15 79,66.22 79,68.32 P8.273
PF_14/LP1_D2: length 47.4
  TOP w0.14: U1.G4 v1(47.75,46.22)
  L5_SIG2 w0.114: v1(56.34,44.88) 56.34,45.71 59.96,49.33 61.05,49.33 64.39,52.67 65.27,52.67 67.97,55.37 72.07,55.37 79.01,62.31 v1(79.01,63.87)
  BOTTOM w0.14: v1(47.75,46.22) 48.16,45.81 48.16,45.21 48.34,45.03 48.74,45.03 48.95,44.83 48.95,44.43 49.16,44.22 52.75,44.22 53.42,44.88 v1(56.34,44.88) ; v1(79.01,63.87) 79.5,64.36 P8.275
PF_15/LP1_D3: length 49.6
  TOP w0.14: U1.H4 v1(47.75,47.02)
  L5_SIG2 w0.114: v1(47.75,47.02) 48.16,47.42 48.16,47.98 48.39,48.21 49.48,48.21 49.91,48.64 51.87,48.64 56.4,53.17 57.29,53.17 57.79,53.68 57.79,55.81 59.77,57.78 63.71,57.78 70.61,64.68 72.78,64.68 74.13,66.03 74.13,66.76 74.33,66.96 74.72,66.96 75.29,66.4 75.29,64.82 75.7,64.41 78.05,64.41 78.65,65.01 78.81,65.01 79.83,65.01 v1(80.21,64.63)
  BOTTOM w0.14: P8.277 80,66.76 79.83,66.6 79.83,65.01 v1(80.21,64.63)
PG_00/ETH0_MDC: length 13.2
  TOP w0.14: U1.W13 v1(39.75,56.62)
  BOTTOM w0.14: P8.125 42,64.32 40.41,62.74 40.41,59.61 40.16,59.36 40.16,57.02 v1(39.75,56.62)
PG_01/ETH0_MDIO: length 16.9
  TOP w0.14: U1.V14 v1(38.95,55.82)
  L3_SIG1 w0.114: v1(39.9,62.6) 39.9,60.99 41.22,59.66 41.22,55.85 40.79,55.42 U1.V14 v1(38.95,55.82)
  BOTTOM w0.14: P8.123 41.5,64.61 39.9,63.02 v1(39.9,62.6)
PG_02/ETH0_RXD0: length 18.6
  TOP w0.14: U1.Y13 v1(39.75,57.42)
  L3_SIG1 w0.114: v1(39.75,57.42) 39.36,57.81 38.79,57.81 38.57,58.02 38.57,59.17 34.66,63.07 30.88,63.07 29.37,64.59 29.37,65.94 29.98,66.55 v1(30,66.55)
  BOTTOM w0.14: P8.77 v1(30,66.55)
PG_03/ETH0_RXD1: length 17.8
  TOP w0.14: U1.AA13 v1(39.75,58.22)
  L3_SIG1 w0.114: v1(39.75,58.22) 39.34,58.62 39.34,59.21 35.15,63.4 33.02,63.4 32.46,63.96 30.56,63.96 29.61,64.9 29.61,65.7 v1(30,66.09)
  BOTTOM w0.14: v1(30,66.09) 30.25,66.09 30.5,66.33 P8.79
PG_04/ETH0_RXCLK_REFCLK: length 18.7
  TOP w0.14: U1.W12 v1(40.55,56.62)
  L3_SIG1 w0.114: v1(32,66.07) 32.42,66.07 32.54,65.95 32.54,65.3 33.5,64.34 36.96,64.34 37.62,63.68 37.62,62.76 40.93,59.45 40.93,57 v1(40.55,56.62)
  BOTTOM w0.14: P8.87 32.5,66.35 32.21,66.07 v1(32,66.07)
PG_05/ETH0_RXCTL_RXDV: length 20
  TOP w0.14: U1.V13 v1(39.75,55.82)
  L5_SIG2 w0.114: v1(39.75,55.82) 40.15,56.21 42.29,56.21 42.55,56.46 42.55,56.85 42.37,57.02 41.94,57.02 41.63,57.33 41.63,59.08 40.91,59.8 39.32,59.8 35.13,64 35.13,66.42 35.26,66.55 v1(35.5,66.55)
  BOTTOM w0.14: P8.99 v1(35.5,66.55)
PG_06/ETH0_TXD0: length 16.2
  TOP w0.14: U1.Y12 v1(40.55,57.42)
  L3_SIG1 w0.114: v1(36.4,63.55) 36.4,63.07 40.15,59.31 40.15,58.82 40.15,57.82 v1(40.55,57.42)
  BOTTOM w0.14: v1(36.4,63.55) 34.21,63.55 32.59,65.18 32.59,65.96 33,66.37 P8.89
PG_07/ETH0_TXD1: length 14.6
  TOP w0.14: U1.AA12 v1(40.55,58.22)
  L5_SIG2 w0.114: v1(40.55,58.22) 40.17,58.6 38.68,58.6 38.56,58.72 38.56,59.55 33.86,64.25 33.86,66.44 33.74,66.55 v1(33.5,66.55)
  BOTTOM w0.14: P8.91 v1(33.5,66.55)
PG_08/ETH0_RXD2: length 16.1
  TOP w0.14: U1.AB13 v1(39.75,59.02)
  L3_SIG1 w0.114: v1(31,66.55) 30.98,66.55 30.58,66.15 30.58,64.57 30.86,64.29 32.58,64.29 33.15,63.72 35.29,63.72 39.64,59.37 v1(39.75,59.02)
  BOTTOM w0.14: P8.81 v1(31,66.55)
PG_09/ETH0_RXD3: length 17
  TOP w0.14: U1.AB12 v1(40.55,59.02)
  L3_SIG1 w0.114: v1(40.55,59.02) 40.55,59.37 37.16,62.76 37.16,63.5 36.63,64.03 33.28,64.03 32.68,64.64 31.61,64.64 31.5,64.76 31.5,65.98 31.38,66.09 v1(31,66.09)
  BOTTOM w0.14: P8.83 31.5,66.33 31.25,66.09 v1(31,66.09)
PG_10/ETH0_TXCTL_TXEN: length 15.7
  TOP w0.14: U1.Y11 v1(42.15,57.42)
  L5_SIG2 w0.114: v1(42.15,57.42) 42.55,57.81 42.55,59.18 41.16,60.57 39.7,60.57 37.22,63.04 37.22,64.13 36.74,64.62 36.4,64.62 36.12,64.9 36.12,66.44 36.23,66.55 v1(36.5,66.55)
  BOTTOM w0.14: P8.103 v1(36.5,66.55)
PG_11/ETH0_TXCLK: length 14.8
  TOP w0.14: U1.AA11 v1(42.15,58.22)
  L5_SIG2 w0.114: v1(42.15,58.22) 42.15,59.07 41.03,60.19 39.51,60.19 36.78,62.92 36.78,63.75 35.86,64.67 35.86,65.98 35.75,66.09 v1(35.5,66.09)
  BOTTOM w0.14: P8.101 36,66.33 35.75,66.09 v1(35.5,66.09)
PG_12/ETH0_TXD2: length 18
  TOP w0.14: v1(43.07,60.25) 43.07,59.93 U1.AB11
  L8_SIG3 w0.114: v1(43.07,60.25) 37.73,60.25 33.1,64.88 33.1,65.2 33.5,65.6 v1(33.5,66.07)
  BOTTOM w0.14: P8.93 34,66.33 33.73,66.07 v1(33.5,66.07)
PG_13/ETH0_TXD3: length 17
  TOP w0.14: U1.W11 v1(42.15,56.62)
  L5_SIG2 w0.114: v1(42.15,56.62) 41.91,56.62 41.27,57.25 41.27,58.93 40.78,59.42 39.19,59.42 34.14,64.48 34.14,66.44 34.25,66.55 v1(34.5,66.55)
  BOTTOM w0.14: P8.95 v1(34.5,66.55)
PG_14/ETH0_CRS: length 40.3
  TOP w0.14: U1.V10 v1(42.95,55.82)
  L3_SIG1 w0.114: v1(69.55,65.84) 69.2,66 66.89,68.31 50.36,68.31 48.78,66.74 48.78,65.84 44.35,61.4 44.35,60.4 44.93,59.82 44.93,56.46 44.68,56.22 43.35,56.22 v1(42.95,55.82)
  BOTTOM w0.14: v1(69.55,65.84) 70,66.29 P8.237
PG_15_ETH0_RX_ER: length 38.4
  TOP w0.14: U1.AA10 v1(42.95,58.22)
  L3_SIG1 w0.114: v1(42.95,58.22) 42.95,58.9 42.68,59.17 42.68,60.76 48.15,66.22 48.15,67.11 49.99,68.95 68.64,68.95 70.51,67.08 v1(70.51,66.37)
  BOTTOM w0.14: v1(70.51,66.37) 70.5,66.38 P8.239
PH_00/ETH0_COL: length 40.1
  TOP w0.14: U1.W10 v1(42.95,56.62)
  L3_SIG1 w0.114: v1(70.51,65.79) 69.98,66.32 69.98,66.75 68.1,68.63 50.18,68.63 48.46,66.92 48.46,66.03 43.99,61.56 43.99,59.89 43.34,59.24 43.34,57 v1(42.95,56.62)
  BOTTOM w0.14: P8.241 71,66.27 v1(70.51,65.79)
PH_01/ETH0_PHY_INT: length 30.3
  TOP w0.14: U1.V9 v1(43.75,55.82)
  L3_SIG1 w0.114: v1(29,66.07) 29.44,66.51 29.44,66.98 30.15,67.69 40.94,67.69 41.71,66.93 41.71,60.83 42.29,60.25 42.29,58.9 42.55,58.64 42.55,55.62 42.76,55.42 U1.V9 v1(43.75,55.82)
  BOTTOM w0.14: v1(29,66.07) 29.23,66.07 29.5,66.33 P8.75
PH_02/ETH0_PTPCLKIN0: length 15.8
  TOP w0.14: U1.Y10 v1(42.95,57.42)
  L5_SIG2 w0.114: v1(36.5,66.09) 36.82,66.09 36.93,65.98 36.93,65.05 37.6,64.38 37.6,63.23 39.89,60.95 41.29,60.95 43.33,58.9 43.33,58.06 42.95,57.68 v1(42.95,57.42)
  BOTTOM w0.14: P8.105 37,66.32 36.77,66.09 v1(36.5,66.09)
PH_03/ETH0_PTPAUXIN0: length 15.6
  TOP w0.14: U1.Y9 v1(43.75,57.42)
  L5_SIG2 w0.114: v1(43.75,57.42) 44.2,57.86 44.2,59.08 43.89,59.39 43.36,59.39 41.41,61.33 40.02,61.33 38.05,63.3 38.05,64.8 v1(37.67,65.18)
  BOTTOM w0.14: P8.107 37.5,65.35 v1(37.67,65.18)
PH_04/ETH0_PTPPPS1: length 13.7
  TOP w0.14: U1.AB10 43.57,59.64 v1(43.57,60.25)
  L5_SIG2 w0.114: v1(38.5,66.09) 38.5,63.36 40.14,61.71 42.11,61.71 v1(43.57,60.25)
  BOTTOM w0.14: P8.113 39,66.4 38.69,66.09 v1(38.5,66.09)
PH_05/ETH0_PTPPPS0: length 17
  TOP w0.14: U1.W9 v1(43.75,56.62)
  L5_SIG2 w0.114: v1(43.75,56.62) 44.13,57 44.68,57 44.93,57.25 44.93,59.72 42.56,62.09 40.63,62.09 40.44,62.28 40.44,62.64 38.87,64.2 38.87,66.44 38.76,66.55 v1(38.5,66.55)
  BOTTOM w0.14: P8.111 v1(38.5,66.55)
PH_06/UART2_RXB/TM0_ACI3: length 33.3
  TOP w0.14: U1.J2 v1(49.35,47.82) ; P8.210 63.25,66.78 63.07,66.6 63.07,65.96 v1(62.24,65.14)
  L3_SIG1 w0.114: v1(62.24,65.14) 61.9,64.8 61.9,59.51 62.36,59.05 62.36,54.84 v2(60.34,52.82)
  BOTTOM w0.14: v2(60.34,52.82) 58.37,50.85 58.37,48.19 57.65,47.46 55.46,47.46 54.64,46.63 51.28,46.63 50.5,47.42 49.75,47.42 v1(49.35,47.82)
PH_07/UART2_TXB: length 35.6
  TOP w0.14: P8.208 62.75,66.4 v1(62.24,65.9) ; U1.J3 v1(48.55,47.82)
  L3_SIG1 w0.114: v2(60.34,51.99) 62.74,54.39 62.74,59.18 62.26,59.66 62.26,64.44 62.66,64.84 62.66,65.49 v1(62.24,65.9)
  BOTTOM w0.14: v2(60.34,51.99) 58.72,50.37 58.72,47.9 57.78,46.96 55.68,46.96 54.74,46.02 52.15,46.02 51.92,45.8 50.46,45.8 49.89,46.38 49.43,46.38 48.95,46.86 48.95,47.44 48.58,47.82 v1(48.55,47.82)
PH_08/UART2_RTSB: length 38.5
  TOP w0.14: v1(63.07,65.14) 63.39,65.46 63.39,66.41 63.75,66.77 P8.212 ; U1.K4 v1(47.75,48.62)
  L3_SIG1 w0.114: v1(63.07,65.14) 63.07,64.69 62.59,64.21 62.59,59.84 63.09,59.33 63.09,53.92 v2(60.34,51.17)
  BOTTOM w0.14: v1(47.75,48.62) 48.15,48.22 48.15,46.72 48.25,46.62 48.68,46.62 49.33,45.97 49.66,45.97 50.67,44.97 52.74,44.97 53.16,45.39 54.74,45.39 55.8,46.46 58.04,46.46 59.06,47.48 59.06,49.89 v2(60.34,51.17)
PH_09/UART2_CTSB: length 43.7
  TOP w0.14: P8.214 64.25,66.76 63.7,66.22 v1(63.7,65.2) ; U1.K6 v1(46.15,48.62)
  L3_SIG1 w0.114: v2(60.34,50.34) 63.47,53.48 63.47,59.44 62.92,59.99 62.92,64.01 63.7,64.8 v1(63.7,65.2)
  BOTTOM w0.14: v2(60.34,50.34) 59.42,49.43 59.42,46.95 56.85,44.37 53.8,44.37 52.84,43.42 48.38,43.42 48.16,43.64 48.16,44.03 47.97,44.22 46.77,44.22 46.55,44.43 46.55,48.22 v1(46.15,48.62)
PH_10/USB0_STP: length 46.8
  TOP w0.14: U1.AB7 45.33,58.99 v1(45.33,59.63)
  L8_SIG3 w0.114: v1(45.33,59.63) 45.67,59.74 46.79,59.74 47.32,59.21 47.32,56.52 47.6,56.24 47.88,56.24 48.16,55.96 48.16,54.02 48.35,53.82 48.75,53.82 48.95,53.62 48.95,53.22 49.16,53.01 50.37,53.01 50.94,52.44 50.94,51.3 55.47,46.76 56.88,46.76 59.32,44.32 59.32,31.67 63.12,27.87 v2(63.12,24.94)
  BOTTOM w0.14: R205.1 v2(63.12,24.94)
PH_11/USB0_D7: length 60.6
  TOP w0.14: U1.AA9 v1(43.73,58.19)
  L5_SIG2 w0.114: v1(43.73,58.19) 43.73,57.95 43.36,57.59 43.36,56.42 43.13,56.18 42.75,56.18 42.55,55.98 42.55,48.74 43.36,47.93 43.36,47.68 43.61,47.42 43.89,47.42 44.15,47.17 44.15,46.84 44.35,46.63 44.68,46.63 44.96,46.35 44.96,46.05 45.19,45.82 45.47,45.82 45.72,45.57 45.72,45.29 46,45.01 46.33,45.01 46.53,44.81 46.53,44.5 46.81,44.22 47.14,44.22 47.37,43.99 47.37,43.61 47.57,43.41 47.9,43.41 48.13,43.18 48.13,42.87 48.39,42.62 50.2,42.62 50.65,43.08 52.07,43.08 53.73,41.41 53.73,23.41 49,18.68 48.44,18.68 48.17,18.68 47.53,18.03 47.53,17.19 47.95,16.77 49.69,16.77 v2(50.5,17.58)
  BOTTOM w0.14: R194.2 51.77,18.85 v2(50.5,17.58)
PH_12/USB0_D6: length 57.6
  TOP w0.14: U1.AB9 v1(43.73,58.99)
  L8_SIG3 w0.114: v1(43.73,58.99) 43.12,58.99 42.55,58.42 42.55,56.41 42.75,56.21 43.15,56.21 43.36,56.01 43.36,54.03 43.59,53.8 43.89,53.8 44.15,53.54 44.15,53.14 44.27,53.01 44.68,53.01 44.96,52.73 44.96,52.43 45.14,52.25 45.44,52.25 45.72,51.97 45.72,51.56 45.87,51.41 46.33,51.41 46.56,51.18 46.56,50.85 47.57,49.83 47.96,49.83 48.16,49.63 48.16,49.28 48.41,49.02 48.69,49.02 48.95,48.77 48.95,48.46 49.2,48.21 50.34,48.21 54.91,43.64 54.91,42.37 55.45,41.83 55.45,23.24 v2(49.78,17.58)
  BOTTOM w0.14: R195.2 51.49,21.23 51.18,21.23 51,21.06 51,18.8 v2(49.78,17.58)
PH_13/USB0_D5: length 62.2
  TOP w0.14: U1.AB6 v1(46.13,58.99)
  L5_SIG2 w0.114: v2(49.07,17.58) 48.58,17.09 48.08,17.09 47.85,17.32 47.85,17.9 48.3,18.36 49.13,18.36 54.05,23.27 54.05,41.66 52.3,43.41 48.41,43.41 48.13,43.69 48.13,43.97 47.88,44.22 47.6,44.22 47.37,44.45 47.37,44.73 46.28,45.82 45.97,45.82 45.75,46.05 45.75,46.35 45.49,46.61 45.21,46.61 44.93,46.89 44.93,47.17 44.68,47.42 44.42,47.42 44.15,47.7 44.15,47.95 43.92,48.18 43.64,48.18 43.36,48.46 43.36,55.19 43.59,55.42 43.92,55.42 44.15,55.65 44.15,55.96 44.4,56.21 44.72,56.21 44.91,56.4 44.91,56.79 45.14,57.02 45.49,57.02 45.72,57.25 45.72,58.58 v1(46.13,58.99)
  BOTTOM w0.14: v2(49.07,17.58) 50.5,19 50.5,21.38 R196.2
PH_14/USB0_D4: length 60.4
  TOP w0.14: U1.AA6 v1(46.13,58.19)
  L5_SIG2 w0.114: v2(48.36,17.58) 48.83,18.04 49.27,18.04 54.37,23.14 54.37,41.9 52.43,43.84 50.72,43.84 50.34,44.22 48.39,44.22 48.13,44.48 48.13,44.81 47.9,45.03 47.55,45.03 46.53,46.05 46.53,46.38 46.28,46.63 46,46.63 45.75,46.89 45.75,47.17 45.49,47.42 45.21,47.42 44.96,47.68 44.96,47.96 44.73,48.18 44.45,48.18 44.15,48.49 44.15,54.79 44.91,55.55 44.91,55.93 45.19,56.21 45.63,56.21 45.75,56.32 45.75,56.69 46.05,57 46.3,57 46.48,57.18 46.48,57.84 v1(46.13,58.19)
  BOTTOM w0.14: v2(48.36,17.58) 49.99,19.2 49.99,21.62 51,22.63 51,23.5 51.31,23.8 R197.2
PH_15/USB0_NXT: length 42.2
  TOP w0.14: v1(44.45,59.63) 44.45,58.92 U1.AB8
  L8_SIG3 w0.114: v2(60.15,28.43) 58.94,29.63 58.94,44.25 56.79,46.41 55.32,46.41 50.56,51.17 50.56,51.99 50.33,52.22 49.19,52.22 48.95,52.46 48.95,52.78 48.72,53.01 48.41,53.01 48.13,53.29 48.13,53.57 47.88,53.82 47.6,53.82 47.35,54.08 47.35,55.98 46.56,56.77 46.56,58.37 46.33,58.6 44.97,58.6 44.45,59.11 v1(44.45,59.63)
  BOTTOM w0.14: R202.2 v2(60.15,28.43)
PI_00/USB0_DIR: length 43.2
  TOP w0.14: U1.AA7 v1(45.33,58.19)
  L8_SIG3 w0.114: v2(62.43,26.97) 59.7,26.97 58.5,28.18 58.5,43.54 57.91,44.12 56.53,44.12 49.86,50.79 49.86,51.17 49.59,51.44 49.17,51.44 48.95,51.66 48.95,51.99 48.72,52.22 48.39,52.22 48.13,52.48 48.13,52.81 47.93,53.01 47.57,53.01 47.37,53.21 47.37,53.54 47.09,53.82 46.81,53.82 46.56,54.08 46.56,56.01 46.36,56.21 45.97,56.21 45.75,56.44 45.75,57.78 v1(45.33,58.19)
  BOTTOM w0.14: R203.2 62.43,26.97 v2(62.43,26.97)
PI_01/USB0_D3: length 40
  TOP w0.14: U1.AA8 v1(44.53,58.19)
  L8_SIG3 w0.114: v2(56.21,30.53) 55.83,30.91 55.83,42.14 55.32,42.65 55.32,43.79 50.09,49.02 49.2,49.02 48.95,49.28 48.95,49.58 47.9,50.62 47.55,50.62 47.35,50.83 47.35,51.16 47.09,51.41 46.81,51.41 46.56,51.66 46.56,51.97 46.3,52.22 46,52.22 45.77,52.45 45.77,52.76 45.52,53.01 45.21,53.01 44.93,53.29 44.93,53.57 44.68,53.82 44.37,53.82 44.15,54.05 44.15,55.98 43.92,56.21 43.59,56.21 43.36,56.44 43.36,57.68 43.49,57.81 44.15,57.81 v1(44.53,58.19)
  BOTTOM w0.14: v2(56.21,30.53) 53.8,28.12 53.8,28.11 R198.2
PI_02/USB0_D2: length 38.3
  TOP w0.14: U1.Y8 v1(44.53,57.39)
  L8_SIG3 w0.114: v2(57.16,30.53) 56.97,31.01 56.97,42.27 56.64,42.6 56.08,42.6 55.77,42.91 55.77,43.87 49.61,50.03 49.01,50.03 48.16,50.88 48.16,51.16 47.9,51.41 47.6,51.41 47.35,51.66 47.35,51.97 47.14,52.17 46.84,52.17 46.56,52.45 46.56,52.76 46.3,53.01 46.02,53.01 45.75,53.29 45.75,53.54 45.49,53.8 45.26,53.8 44.93,54.13 44.93,55.96 44.7,56.18 44.37,56.18 44.15,56.41 44.15,57.01 v1(44.53,57.39)
  BOTTOM w0.14: R199.2 54.81,27.98 54.81,28.24 57.1,30.53 v2(57.16,30.53)
PI_03/USB0_D1: length 38.6
  TOP w0.14: U1.Y7 v1(45.35,57.42)
  L8_SIG3 w0.114: v2(57.99,30.53) 57.99,43.33 57.58,43.74 56.4,43.74 49.73,50.41 49.42,50.41 48.95,50.88 48.95,51.18 48.69,51.44 48.36,51.44 48.13,51.66 48.13,51.99 47.9,52.22 47.57,52.22 47.35,52.45 47.35,52.78 47.12,53.01 46.79,53.01 46.53,53.26 46.53,53.57 46.28,53.82 46,53.82 45.75,54.08 45.75,55.96 45.49,56.21 45.16,56.21 44.93,56.44 44.93,57 v1(45.35,57.42)
  BOTTOM w0.14: v2(57.99,30.53) 55.7,28.24 R200.2
PI_04/USB0_D0: length 39.4
  TOP w0.14: U1.W7 v1(45.33,56.59)
  L10_SIG4 w0.114: v2(57.99,29.45) 58.05,29.45 59,30.4 59,38.71 55.65,42.06 55.65,42.67 52.49,45.83 50.62,45.83 49.85,46.61 48.44,46.61 48.13,46.91 48.13,47.17 47.88,47.42 47.6,47.42 47.35,47.68 47.35,47.98 47.12,48.21 46.79,48.21 46.56,48.44 46.56,48.69 46.23,49.02 45.97,49.02 45.75,49.25 45.75,54.36 46.02,54.64 46.3,54.64 46.53,54.86 46.53,55.17 46.33,55.37 46,55.37 45.75,55.63 45.75,56.18 v1(45.33,56.59)
  BOTTOM w0.14: R201.2 56.85,28.31 v2(57.99,29.45)
PI_05/USB0_CLK: length 77.1
  TOP w0.14: U1.W8 v1(44.53,56.59)
  L3_SIG1 w0.114: v2(48.34,16.31) 48.84,15.8 50.75,15.8 52.86,17.91 62.26,17.91 v2(63.32,18.97)
  L10_SIG4 w0.114: v2(63.32,18.97) 55.45,26.85 55.45,40.75 51.38,44.82 50.97,44.82 49.96,45.82 48.35,45.82 48.16,46.02 48.16,46.41 47.96,46.61 47.6,46.61 47.35,46.86 47.35,47.19 47.12,47.42 46.75,47.42 46.53,47.64 46.53,47.98 46.3,48.21 45.97,48.21 45.75,48.44 45.75,48.77 45.49,49.02 45.14,49.02 44.96,49.2 44.96,54.36 45.21,54.61 45.49,54.61 45.72,54.84 45.72,55.17 45.49,55.4 45.16,55.4 44.93,55.63 44.93,56.19 v1(44.53,56.59)
  BOTTOM w0.14: v2(63.32,18.97) 62.94,19.35 R64.1 ; R65.1 51.49,24.66 51.23,24.66 50.5,23.93 50.5,22.89 49.48,21.87 49.48,19.48 47.83,17.83 47.83,16.81 v2(48.34,16.31)
PWR_RESET: length 4.2
  BOTTOM w0.14: U16.3 9.61,30.02 8.33,31.3 R124.1
SD_CARD_EN*: length 38.9
  TOP w0.14: v2(46.69,1.54) 46.41,1.82 U4.6
  L3_SIG1 w0.114: v2(26.62,8.31) 27.79,9.47 27.79,12.4 30.05,14.66 v2(30.05,16.05)
  L10_SIG4 w0.114: v2(26.62,8.31) 33.22,1.7 44.53,1.7 45.03,2.21 46.02,2.21 v2(46.69,1.54)
  BOTTOM w0.14: v2(30.05,16.05) 30.05,16.75 29.1,17.69 U7.15 ; U8.15 25.87,10.2 26.62,9.45 v2(26.62,8.31)
SYS_CLKIN0: length 5.2
  TOP w0.14: U1.K1 50.71,48.06 52.27,48.06 ; R114.2 52.27,45.78 52.27,48.06 ; 52.27,48.06 R142.2
SYS_CLKOUT: length 7.7
  TOP w0.14: TP26.1 v1(31.76,49.07) ; U1.L17 v1(36.55,49.42)
  L8_SIG3 w0.114: v1(31.76,49.07) 32.13,48.92 33.43,48.92 33.76,49.25 33.76,49.59 34.03,49.86 36.11,49.86 v1(36.55,49.42)
SYS_FAULT: length 8.9
  TOP w0.14: R67.1 26.72,38.71 27.02,38.71 DS10.A 30.15,39.96 TP25.1 31.57,41.33 31.57,42.04 U1.C22
SYS_FAULT*: length 88.2
  TOP w0.14: P8.276 79.75,66.62 v1(80.21,66.15) ; U1.G19 v1(34.95,46.22)
  TOP w0.381: v2(31.06,44.88) TP1.1 R8.2 R7.2
  L3_SIG1 w0.114: v2(31.06,44.88) 32,45.82 34.28,45.82 34.61,46.14 v1(34.95,46.22)
  L5_SIG2 w0.114: v1(34.95,46.22) U1.G19 35.92,46.62 36.15,46.84 36.15,48.85 36.32,49.02 37.54,49.02 37.75,49.23 37.75,59.73 32.4,65.09 32.4,66.66 33.48,67.74 40.74,67.74 41.5,66.98 41.5,65.76 42.32,64.95 43.33,64.95 47.02,68.63 77.74,68.63 v1(80.21,66.15)
SYS_HWRST*: length 120
  TOP w0.14: U1.J17 v1(36.55,47.82) ; v2(32.59,15.93) 33.49,16.82 R157.1 ; R160.2 v2(61.8,58.22) ; U4.20 42.38,5.25 v2(41.99,5.64) R17.2
  L3_SIG1 w0.114: v2(61.8,58.22) 59.24,58.22 51.13,50.11 50.06,50.11 49.77,50.41 49.1,50.41 48.97,50.53 48.13,50.53 47.97,50.37 46.53,50.37 46.3,50.6 44.35,50.6 44.17,50.42 44.17,50.09 43.89,49.81 43.56,49.81 43.36,49.61 43.36,49.3 42.27,48.21 36.94,48.21 v1(36.55,47.82) ; v2(41.99,5.64) 40.97,5.64 37.67,8.94 33.86,8.94 32.59,10.21 v2(32.59,15.93) ; v2(19.15,38.83) v2(22.15,38.83)
  L5_SIG2 w0.114: v2(32.59,15.93) 31.06,17.45 31.06,21.74 26.62,26.19 26.62,31.8 24.46,33.96 23.06,33.96 22.15,34.87 v2(22.15,38.83)
  L8_SIG3 w0.114: v1(36.55,47.82) 36.14,48.22 36.14,48.84 35.96,49.02 34.01,49.02 33.58,48.59 29.11,48.59 26.37,51.33 22.72,51.33 v2(22.15,51.91)
  L10_SIG4 w0.114: v2(22.15,51.91) 22.15,46.18 22.68,45.64 22.68,39.36 v2(22.15,38.83)
  BOTTOM w0.14: v2(61.8,58.22) 63,57.02 R159.2 63.91,55.41 U21.8 ; U5.A2 v2(19.15,38.83) ; U5.A4 v2(22.15,38.83) ; U6.A4 v2(22.15,51.91)
SYS_RESOUT*: length 7.6
  TOP w0.14: v2(30.56,42.28) TP2.1 R9.2 ; U1.E20 v1(34.15,44.62)
  L3_SIG1 w0.114: v1(34.15,44.62) 34.07,44.26 33.75,43.94 33.75,43.58 33.59,43.42 31.69,43.42 v2(30.56,42.28)
SYS_XTAL0: length 2.9
  TOP w0.14: R143.1 50.75,51.61 U1.M1
TARGET_RESET*: length 73.5
  TOP w0.14: v1(80.21,65.39) 79.58,66.03 79.58,66.28 79.25,66.61 P8.274 ; v1(47.32,65.96) 47.13,66.15 47.13,66.73 47.25,66.84 P8.146
  L5_SIG2 w0.114: v1(47.32,65.96) 47.95,65.96 50.29,68.3 77.55,68.3 79.63,66.22 79.63,65.98 v1(80.21,65.39)
  L8_SIG3 w0.114: v2(75.4,42.71) 76.78,44.1 76.78,53.72 v2(75.4,55.11) 75.4,57.26 79.45,61.32 79.45,64.63 v1(80.21,65.39)
  BOTTOM w0.14: U18.2 72.28,55.93 R123.2 72.53,55.24 72.67,55.11 v2(75.4,55.11) JP1.1 ; R5.1 v2(75.4,42.71)
UART0_EN*: length 56.6
  TOP w0.14: U4.7 47.68,3.25 v2(48.08,2.84) ; v2(75.64,32.56) R81.2 R82.1 77.58,31.7 v2(77.58,32.56)
  L3_SIG1 w0.114: v2(75.64,32.56) 71.12,32.56 63.89,25.34 63.89,23.23 64.87,22.25 64.87,18.88 62.83,16.84 62.24,16.84 61.92,16.84 55.93,16.84 55.91,16.81 47.47,8.38 47.47,3.45 v2(48.08,2.84)
  BOTTOM w0.14: U29.10 75.63,32.55 v2(75.64,32.56) ; U29.13 v2(77.58,32.56)
UART0_FLOW_EN*: length 57.1
  TOP w0.14: U4.8 v2(48.11,3.75) ; v2(78.23,24.09) 78.23,25 R83.2 R84.1 76.28,25.07 v2(76.28,23.04)
  L3_SIG1 w0.114: v2(76.28,23.04) 76.28,24.58 74.9,25.96 65.09,25.96 64.26,25.13 64.26,23.49 65.19,22.57 65.19,18.75 62.24,15.8 55.59,15.8 48.11,8.33 v2(48.11,3.75)
  BOTTOM w0.14: U29.1 v2(78.23,24.09) ; U29.4 v2(76.28,23.04)
UART_3V3_IO: length 14.4
  TOP w0.305: 69.56,20.43 U14.6
  TOP w0.508: R87.1 v2(73.73,24.07) ; TP18.1 v2(70.64,20.06) C93.1 69.56,20.43 ; R89.1 R88.1 79.65,18.33 80.16,17.82 v2(80.16,16.93) ; DS7.A v2(69.17,34.02) ; DS8.A v2(67.39,34.02)
  BOTTOM w0.305: U13.14 78.23,17.24 78.54,16.93
  BOTTOM w0.508: v2(80.16,16.93) C91.1 78.54,16.93 ; v2(70.64,20.06) 69.9,20.06 C92.1
UNNAMED_7_CAP_I120_N1: length 6.9
  TOP w0.305: P3.B9 53.41,9.32 P3.A4 53.41,11.23 53.39,11.25 53.39,11.25 52.98,11.67 D8.C ; C257.1 55.91,11.83 P3.A9 55.91,9.32 P3.B4
UNNAMED_7_CAP_I130_N1: length 28.4
  TOP w0.508: P3.SH4 51.24,2.24 ; P3.SH4 49.54,2.24 ; P3.SH4 49.54,4.55 ; P3.SH4 51.24,4.55 ; 54.3,2.84 P3.SH6 ; P3.SH6 54.66,2.09 ; P3.SH6 55.02,2.84 ; P3.SH6 54.66,3.59 ; P3.SH3 59.78,4.55 ; P3.SH3 58.08,2.24 ; P3.SH3 59.78,2.24 ; P3.SH3 58.08,4.55 ; 60.87,6.32 C258.1 ; C258.1 60.87,7.49 ; C258.1 60.32,6.91 ; 60.77,7.94 R211.1 ; R211.1 60.12,8.69 ; R211.1 60.77,9.44 ; P3.SH5 54.66,6.69 ; P3.SH5 55.02,5.94 ; P3.SH5 54.3,5.94 ; P3.SH5 54.66,5.19 ; 49.54,6.97 P3.SH1 ; P3.SH1 49.54,9.28 ; P3.SH1 51.24,6.97 ; 58.08,6.97 P3.SH2 ; P3.SH2 59.78,6.97 ; P3.SH2 59.78,9.28
UNNAMED_7_CN2P_I131_N2: length 1.7
  TOP w0.14: S1.1B 54.17,32.19 R212.1
UNNAMED_7_CN24PAB2GND6SHLD_I123: length 18.7
  TOP w0.305: P3.A5 53.91,11.75 v2(53.63,12.03)
  BOTTOM w0.305: v2(53.63,12.03) 53.63,11.23 53.14,10.74 50.57,10.74 49,9.17 49,7.21 50.42,5.79 53.67,5.79 54.01,5.45 D6.3 54.01,3.74 53.14,2.87 R208.1
UNNAMED_7_CN24PAB2GND6SHLD_I126: length 6.6
  BOTTOM w0.305: P3.B5 55.46,7.86 55.91,7.42 55.91,6.02 55.31,5.43 D6.1 55.31,3.74 56.18,2.87 R209.1
UNNAMED_7_ICMIC20X5_I8_EN: length 4.7
  TOP w0.14: U23.1 R221.2 R193.2 R103.1
UNNAMED_7_ICUSB331X_I85_DATA0: length 2.5
  BOTTOM w0.14: R201.1 57.22,26.35 U22.16
UNNAMED_7_ICUSB331X_I85_DATA1: length 2.7
  BOTTOM w0.14: R200.1 56.72,25.71 U22.15
UNNAMED_7_ICUSB331X_I85_DATA2: length 3.6
  BOTTOM w0.14: U22.14 56.22,25.44 55.7,25.96 54.74,25.96 54.56,26.14 R199.1
UNNAMED_7_ICUSB331X_I85_DATA3: length 4.1
  BOTTOM w0.14: U22.13 55.72,25.15 55.42,25.45 53.98,25.45 53.42,26.01 R198.1
UNNAMED_7_ICUSB331X_I85_DATA4: length 2.5
  BOTTOM w0.14: R197.1 53.42,23.15 U22.11
UNNAMED_7_ICUSB331X_I85_DATA5: length 2.2
  BOTTOM w0.14: R196.1 54.97,22.66 U22.10
UNNAMED_7_ICUSB331X_I85_DATA6: length 2.5
  BOTTOM w0.14: U22.9 53.41,22.15 R195.1
UNNAMED_7_ICUSB331X_I85_DATA7: length 2.7
  BOTTOM w0.14: U22.8 54.06,21.65 R194.1
UNNAMED_7_ICUSB331X_I85_DIR: length 4.2
  BOTTOM w0.14: R203.1 60.91,26.09 59.89,25.07 59.89,23.83 59.72,23.65 U22.19
UNNAMED_7_ICUSB331X_I85_NXT: length 3.6
  BOTTOM w0.14: R202.1 60.15,26.09 59.26,25.2 58.4,25.2 58.22,25.02 U22.18
UNNAMED_7_ICUSB331X_I85_RBIAS: length 4.6
  BOTTOM w0.14: U22.24 60,21.15 60.78,20.37 60.78,18.91 61.43,18.26 R206.1
UNNAMED_7_ICUSB331X_I85_STP: length 3.8
  BOTTOM w0.14: R205.2 60.71,24.94 60.4,24.64 60.4,23.55 60.01,23.15 U22.20
UNNAMED_7_ICUSB331X_I85_VBUS: length 2.7
  BOTTOM w0.14: U22.2 57.72,19.29 57.94,19.08 58.4,19.08 R218.2
UNNAMED_7_RES_I185_N1: length 5.2
  BOTTOM w0.14: R217.1 63.32,20.5 64.08,19.74 64.08,17.1 Y4.3
USB_DM: length 14.5
  TOP w0.133: P2.A7 v1(69.06,11.54) 68.94,11.66 68.94,17.07 69.07,17.21 ; 69.07,17.21 D1.3 ; 69.07,17.21 68.94,17.34 68.94,20.64 69.06,20.76 U14.5
  BOTTOM w0.133: v1(69.06,11.54) 69.06,9.92 P2.B7
USB_DP: length 13.5
  TOP w0.133: U14.4 68.56,20.76 68.68,20.64 68.68,17.34 68.55,17.21 ; 68.55,17.21 68.55,17.21 68.68,17.07 68.68,11.63 68.56,11.51 P2.A6 68.64,10.44 68.64,9.85 68.68,9.8 68.68,9.8 P2.B6 ; 68.55,17.21 D1.4
USB_PHY_CLKOUT: length 2.7
  BOTTOM w0.14: U22.12 54.06,23.65 R65.2
USB_PHY_DM: length 14.6
  TOP w0.133: v1(55.04,12.79) 54.79,12.54 54.79,11.39 54.91,11.27 P3.A7
  BOTTOM w0.133: U22.5 56.22,19.75 56.1,19.63 56.1,19.14 54.79,17.83 54.79,13.04 v1(55.04,12.79) 54.69,12.44 54.69,10.24 54.26,9.81 P3.B7
